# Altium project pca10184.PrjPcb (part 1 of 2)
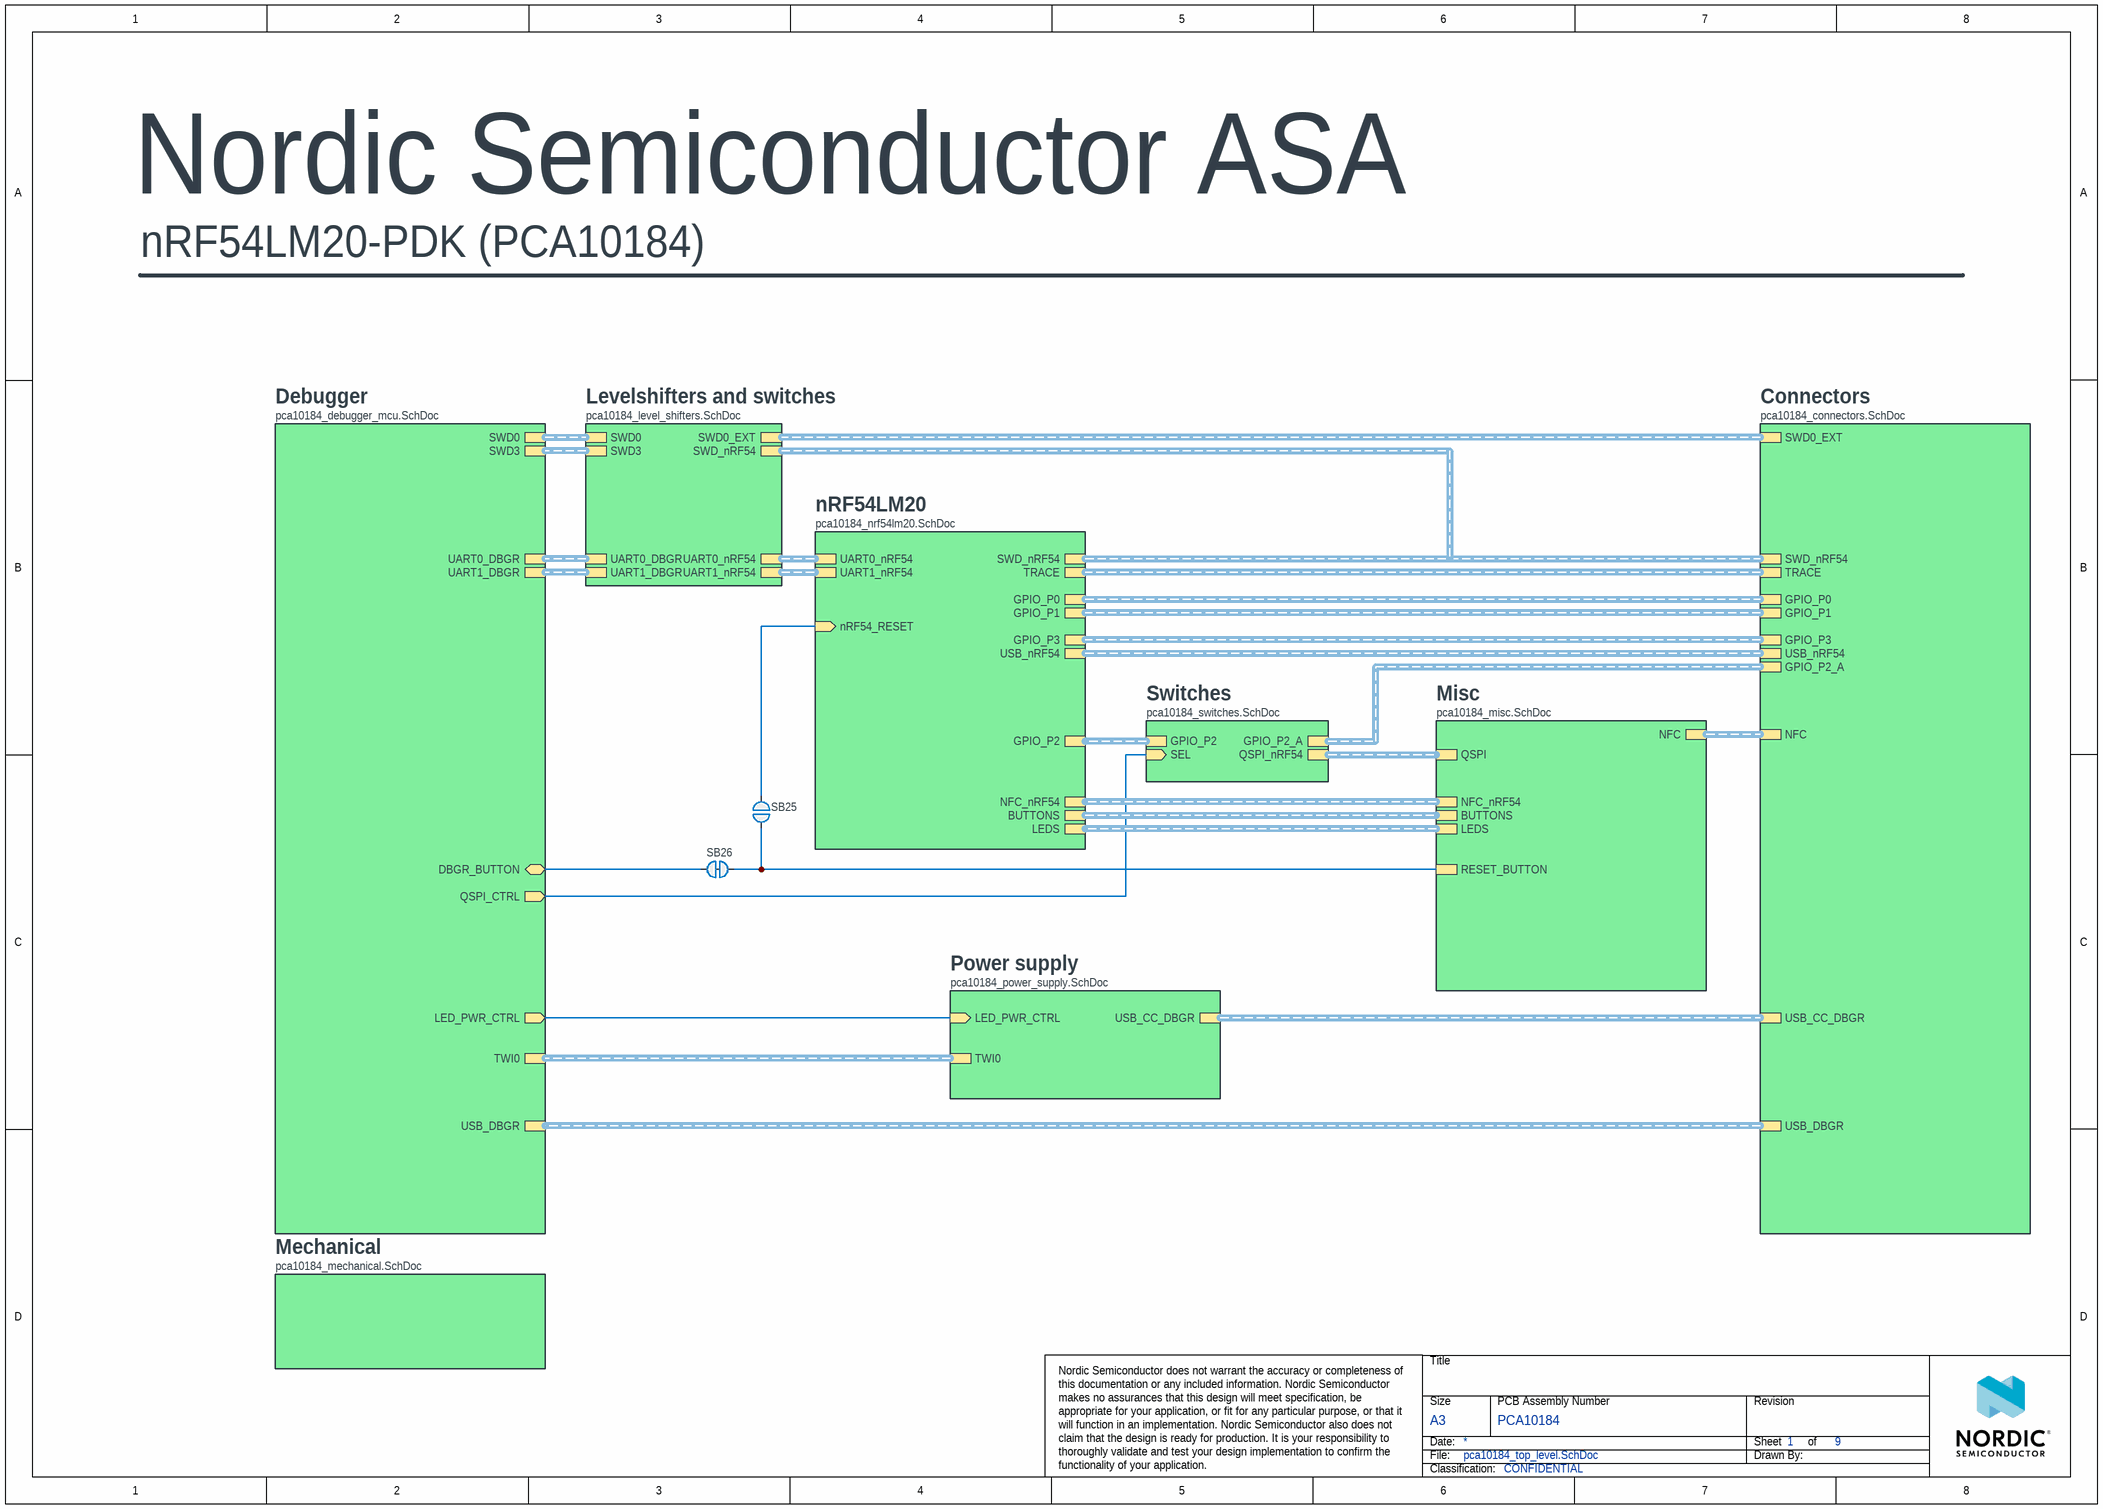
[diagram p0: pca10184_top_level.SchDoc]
SurfaceFinish: ENIG; SoldermaskColor: Blue; SilkscreenColor: White; ProductName: nRF54LM20 Preview Development Kit; PCBRevision: 0227GETR; PCBNumber: 400861; PCARevision: 0.3.4; PCAName: PCA10184; Organization: Nordic Semiconductor; NrOfLayers: 8; Dielectric: FR-4; Designer: GETR; Compliance: RoHS, REACH, Halogen-Free; Classification: CONFIDENTIAL; BoardTitle: nRF54LM20-PDK; BoardThickness: 1.6 mm
9 sheets, 284 parts. Net scope: hierarchical (ports join the sheet entries above them; power ports are global).
Board files: 400861.PcbDoc, 400861_panel.PcbDoc
Sheets:
  pca10184_top_level.SchDoc
    Debugger = pca10184_debugger_mcu.SchDoc
    Power supply = pca10184_power_supply.SchDoc
    nRF54LM20 = pca10184_nrf54lm20.SchDoc
    Connectors = pca10184_connectors.SchDoc
    Mechanical = pca10184_mechanical.SchDoc
    Misc = pca10184_misc.SchDoc
    Levelshifters and switches = pca10184_level_shifters.SchDoc
    Switches = pca10184_switches.SchDoc

## Sheet pca10184_top_level.SchDoc: =ProductName
size A3; Author: GETR; CompanyName: Nordic Semiconductor; DrawnBy: GETR; DocumentNumber: 1; Revision: 0.3.4; SheetNumber: 1; SheetTotal: 9

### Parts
SB25  Solderbridge  [Solderbridge]  (value not drawn)  (no BOM)
SB26  Solderbridge  [Solderbridge_Shorted]  (value not drawn)  (net tie, no BOM)

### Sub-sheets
Connectors = pca10184_connectors.SchDoc: SWD_nRF54 (harness SWD), NFC (harness NFC), GPIO_P0 (harness GPIO_P0), GPIO_P1 (harness GPIO_P1), GPIO_P3 (harness GPIO_P3), SWD0_EXT (harness SWD), USB_nRF54 (harness USB), USB_DBGR (harness USB), USB_CC_DBGR (harness USB_CC), TRACE (harness TRACE), GPIO_P2_A (harness GPIO_P2)
Debugger = pca10184_debugger_mcu.SchDoc: UART0_DBGR (harness UART_DBGR), UART1_DBGR (harness UART_DBGR), SWD0 (harness SWD), SWD3 (harness SWD), USB_DBGR (harness USB), TWI0 (harness TWI), DBGR_BUTTON (bidir), LED_PWR_CTRL (out), QSPI_CTRL (out)
Levelshifters and switches = pca10184_level_shifters.SchDoc: SWD0 (harness SWD), SWD0_EXT (harness SWD), UART0_nRF54 (harness UART), UART1_nRF54 (harness UART), SWD3 (harness SWD), SWD_nRF54 (harness SWD), UART0_DBGR (harness UART_DBGR), UART1_DBGR (harness UART_DBGR)
Mechanical = pca10184_mechanical.SchDoc: no entries
Misc = pca10184_misc.SchDoc: NFC_nRF54 (harness NFC), NFC (harness NFC), BUTTONS (harness BUTTONS), LEDS (harness LEDS), QSPI (harness QSPI), RESET_BUTTON
nRF54LM20 = pca10184_nrf54lm20.SchDoc: GPIO_P0 (harness GPIO_P0), GPIO_P1 (harness GPIO_P1), GPIO_P2 (harness GPIO_P2), GPIO_P3 (harness GPIO_P3), USB_nRF54 (harness USB), BUTTONS (harness BUTTONS), LEDS (harness LEDS), NFC_nRF54 (harness NFC), UART0_nRF54 (harness UART), UART1_nRF54 (harness UART), SWD_nRF54 (harness SWD), TRACE (harness TRACE), nRF54_RESET (in)
Power supply = pca10184_power_supply.SchDoc: TWI0 (harness TWI), LED_PWR_CTRL (in), USB_CC_DBGR (harness USB_CC)
Switches = pca10184_switches.SchDoc: GPIO_P2 (harness GPIO_P2), GPIO_P2_A (harness GPIO_P2), QSPI_nRF54 (harness QSPI), SEL (in)

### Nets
DBGR_BUTTON: SB26.2 ; sheet Debugger/DBGR_BUTTON
LED_PWR_CTRL: sheet Debugger/LED_PWR_CTRL, sheet Power supply/LED_PWR_CTRL
nRF54_RESET: SB25.1 ; sheet nRF54LM20/nRF54_RESET
QSPI_CTRL: sheet Debugger/QSPI_CTRL, sheet Switches/SEL
NetSB22_1: SB25.2 SB26.1 ; sheet Misc/RESET_BUTTON

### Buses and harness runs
harness sheet Connectors/GPIO_P0 = sheet nRF54LM20/GPIO_P0
harness sheet Connectors/GPIO_P1 = sheet nRF54LM20/GPIO_P1
harness sheet Connectors/GPIO_P2_A = sheet Switches/GPIO_P2_A
harness sheet Connectors/GPIO_P3 = sheet nRF54LM20/GPIO_P3
harness sheet Connectors/NFC = sheet Misc/NFC
harness sheet Connectors/SWD0_EXT = sheet Levelshifters and switches/SWD0_EXT
harness sheet Connectors/SWD_nRF54 = sheet Levelshifters and switches/SWD_nRF54 = sheet nRF54LM20/SWD_nRF54
harness sheet Connectors/TRACE = sheet nRF54LM20/TRACE
harness sheet Connectors/USB_CC_DBGR = sheet Power supply/USB_CC_DBGR
harness sheet Connectors/USB_DBGR = sheet Debugger/USB_DBGR
harness sheet Connectors/USB_nRF54 = sheet nRF54LM20/USB_nRF54
harness sheet Debugger/SWD0 = sheet Levelshifters and switches/SWD0
harness sheet Debugger/SWD3 = sheet Levelshifters and switches/SWD3
harness sheet Debugger/TWI0 = sheet Power supply/TWI0
harness sheet Debugger/UART0_DBGR = sheet Levelshifters and switches/UART0_DBGR
harness sheet Debugger/UART1_DBGR = sheet Levelshifters and switches/UART1_DBGR
harness sheet Levelshifters and switches/UART0_nRF54 = sheet nRF54LM20/UART0_nRF54
harness sheet Levelshifters and switches/UART1_nRF54 = sheet nRF54LM20/UART1_nRF54
harness sheet Misc/BUTTONS = sheet nRF54LM20/BUTTONS
harness sheet Misc/LEDS = sheet nRF54LM20/LEDS
harness sheet Misc/NFC_nRF54 = sheet nRF54LM20/NFC_nRF54
harness sheet Misc/QSPI = sheet Switches/QSPI_nRF54
harness sheet nRF54LM20/GPIO_P2 = sheet Switches/GPIO_P2

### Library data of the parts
SB25 = Solderbridge: Manufacturer: N.A.; Part number NEMS: 100500458; Pad Count: 2; Component Status: Active; System: Connector
SB26 = Solderbridge Shorted: Shorted Solderbridge; Manufacturer: N.A.; Part number NEMS: 100500459; Pad Count: 2; Component Status: Active; System: Connector

## Sheet pca10184_debugger_mcu.SchDoc: =ProductName + ' - Debugger'
size A3; Author: GETR; CompanyName: Nordic Semiconductor; DrawnBy: GETR; DocumentNumber: 3; Revision: 0.3.4; SheetNumber: 3; SheetTotal: 9
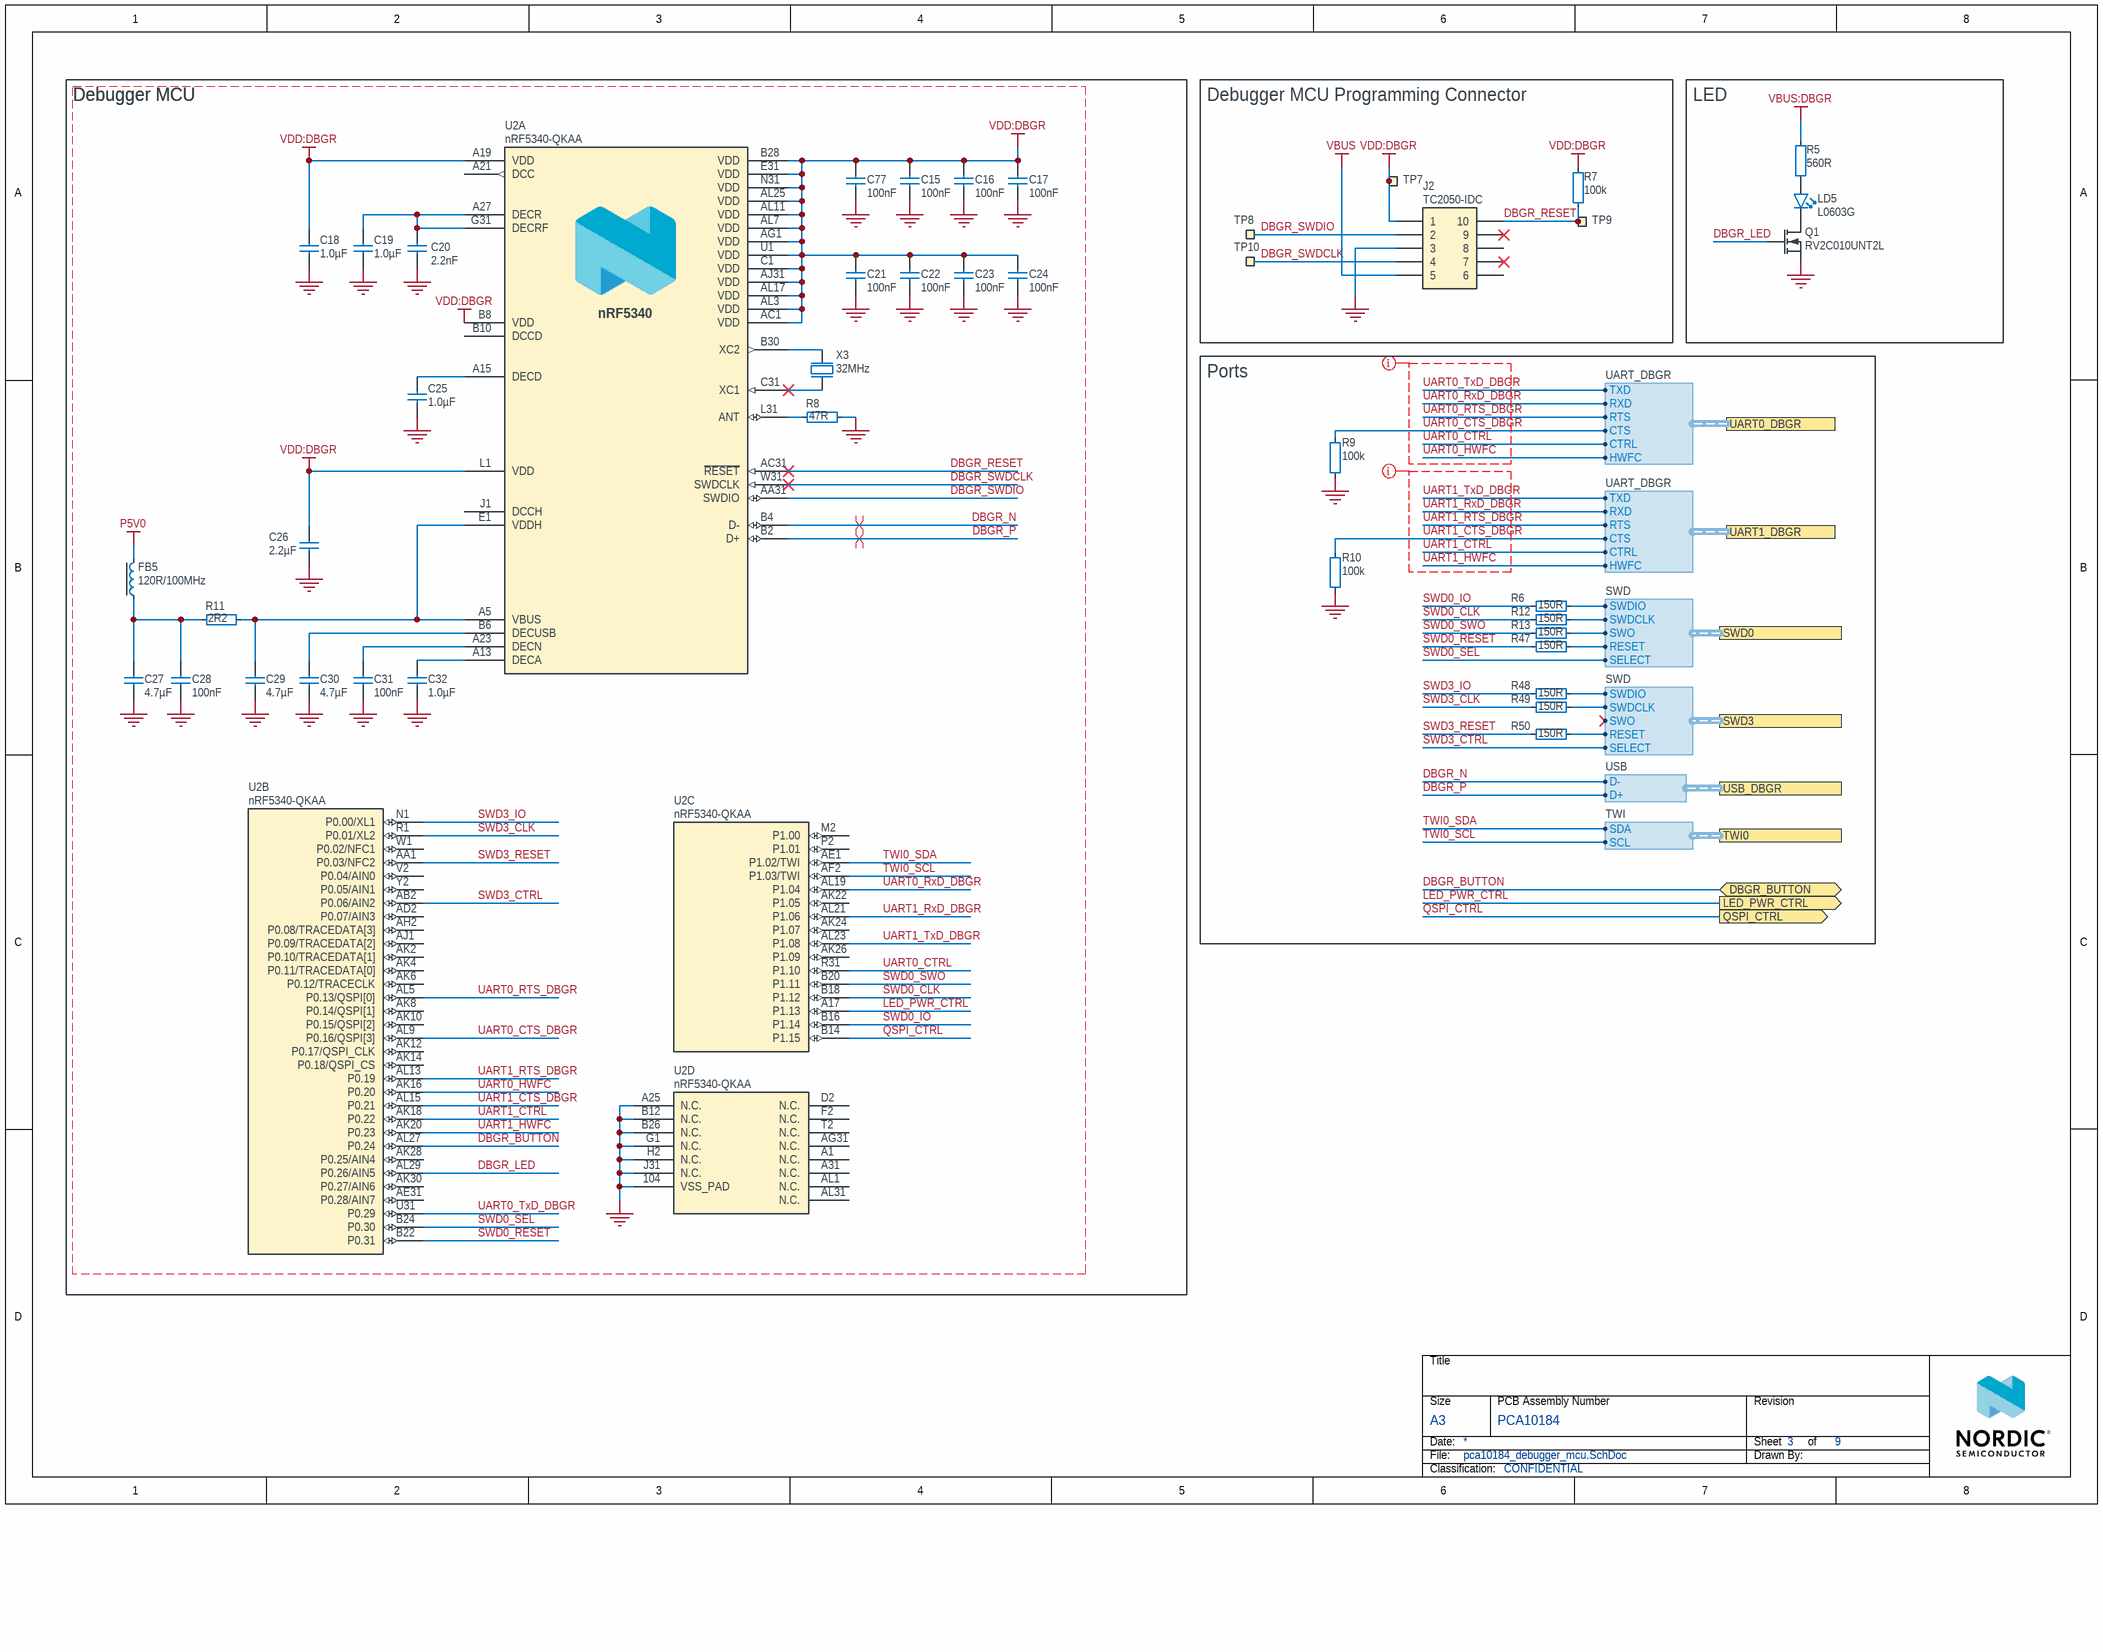
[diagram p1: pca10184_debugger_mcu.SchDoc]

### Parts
C15  100nF  [CAPC0603X03L_C]
C16  100nF  [CAPC0603X03L_C]
C17  100nF  [CAPC0603X03L_C]
C18  1.0µF  [CAPC1005X04L]
C19  1.0µF  [CAPC1005X04L]
C20  2.2nF  [CAPC0603X03L_C]
C21  100nF  [CAPC0603X03L_C]
C22  100nF  [CAPC0603X03L_C]
C23  100nF  [CAPC0603X03L_C]
C24  100nF  [CAPC0603X03L_C]
C25  1.0µF  [CAPC1005X04L]
C26  2.2µF  [CAPC1608X06L]
C27  4.7µF  [CAPC1608X06L]
C28  100nF  [CAPC0603X03L_C]
C29  4.7µF  [CAPC1608X06L]
C30  4.7µF  [CAPC1608X06L]
C31  100nF  [CAPC0603X03L_C]
C32  1.0µF  [CAPC1005X04L]
C77  100nF  [CAPC0603X03L_C]
FB5  120R/100MHz  [INDC1005X04L_C2]
J2  TC2050-IDC  [TC2050-IDC-NLFP]  (no BOM)
LD5  L0603G  [LED_0603_G]
Q1  RV2C010UNT2L  [DFN65P100X40-3L]
R5  560R  [RESC0603X03L_C]
R6  150R  [RESC0603X03L_C]
R7  100k  [RESC0603X03L_C]
R8  47R  [RESC0603X03L_C]
R9  100k  [RESC0603X03L_C]
R10  100k  [RESC0603X03L_C]
R11  2R2  [RESC1608X06L]
R12  150R  [RESC0603X03L_C]
R13  150R  [RESC0603X03L_C]
R47  150R  [RESC0603X03L_C]
R48  150R  [RESC0603X03L_C]
R49  150R  [RESC0603X03L_C]
R50  150R  [RESC0603X03L_C]
TP7  Ø1.5mm,SMD  [TP_SMD_D1.5mm]  (value not drawn)  (no BOM)
TP8  Ø1.5mm,SMD  [TP_SMD_D1.5mm]  (value not drawn)  (no BOM)
TP9  Ø1.5mm,SMD  [TP_SMD_D1.5mm]  (value not drawn)  (no BOM)
TP10  Ø1.5mm,SMD  [TP_SMD_D1.5mm]  (value not drawn)  (no BOM)
U2  nRF5340-QKAA  [AQFN40P700X700X85_HS-99N]  (parts A,B,C,D of 4)
X3  32MHz  [BT-XTAL_2016]

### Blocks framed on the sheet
Debugger MCU Programming Connector: J2 R7 TP7-TP10
LED: LD5 Q1 R5
Ports: R6 R9 R10 R12 R13 R47-R50

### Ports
DBGR_BUTTON (bidir), LED_PWR_CTRL (out), QSPI_CTRL (out), SWD0 (harness SWD), SWD3 (harness SWD), TWI0 (harness TWI), UART0_DBGR (harness UART_DBGR), UART1_DBGR (harness UART_DBGR), USB_DBGR (harness USB)

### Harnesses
UART_DBGR: RTS, CTS, RXD, TXD, HWFC, CTRL
SWD: SWDIO, SWDCLK, SWO, RESET, SELECT
USB: D+, D-
TWI: SCL, SDA

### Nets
GND: C15.2 C16.2 C17.2 C18.2 C19.1 C20.2 C21.2 C22.2 C23.2 C24.2 C25.1 C26.2 C27.2 C28.2 C29.2 C30.2 C31.2 C32.1 C77.2 J2.3 Q1.2(S) R8.2 R9.2 R10.2 U2.104(VSS_PAD) U2.A25(N.C.) U2.B12(N.C.) U2.B26(N.C.) U2.G1(N.C.) U2.H2(N.C.) U2.J31(N.C.) X3.2(GND) X3.4(GND)
P5V0: FB5.2
VBUS: J2.5
VBUS:DBGR: R5.2
VDD:DBGR: C15.1 C16.1 C17.1 C18.1 C21.1 C22.1 C23.1 C24.1 C26.1 C77.1 J2.1 R7.2 TP7.1 U2.A19(VDD) U2.AC1(VDD) U2.AG1(VDD) U2.AJ31(VDD) U2.AL3(VDD) U2.AL7(VDD) U2.AL11(VDD) U2.AL17(VDD) U2.AL25(VDD) U2.B8(VDD) U2.B28(VDD) U2.C1(VDD) U2.E31(VDD) U2.L1(VDD) U2.N31(VDD) U2.U1(VDD)
DBGR_BUTTON: U2.AL27(P0.24) ; port DBGR_BUTTON
DBGR_LED: Q1.1(G) U2.AL29(P0.26/AIN5)
DBGR_N: U2.B4(D-) ; port USB_DBGR.D-
DBGR_P: U2.B2(D+) ; port USB_DBGR.D+
DBGR_RESET: J2.10 R7.1 TP9.1 U2.AC31(~{RESET})
DBGR_SWDCLK: J2.4 TP10.1 U2.W31(SWDCLK)
DBGR_SWDIO: J2.2 TP8.1 U2.AA31(SWDIO)
LED_PWR_CTRL: U2.A17(P1.13) ; port LED_PWR_CTRL
QSPI_CTRL: U2.B14(P1.15) ; port QSPI_CTRL
SWD0_CLK: R12.1 U2.B18(P1.12)
SWD0_IO: R6.1 U2.B16(P1.14)
SWD0_RESET: R47.1 U2.B22(P0.31)
SWD0_SEL: U2.B24(P0.30) ; port SWD0.SELECT
SWD0_SWO: R13.1 U2.B20(P1.11)
SWD3_CLK: R49.1 U2.R1(P0.01/XL2)
SWD3_CTRL: U2.AB2(P0.06/AIN2) ; port SWD3.SELECT
SWD3_IO: R48.1 U2.N1(P0.00/XL1)
SWD3_RESET: R50.1 U2.AA1(P0.03/NFC2)
TWI0_SCL: U2.AF2(P1.03/TWI) ; port TWI0.SCL
TWI0_SDA: U2.AE1(P1.02/TWI) ; port TWI0.SDA
UART0_CTRL: U2.R31(P1.10) ; port UART0_DBGR.CTRL
UART0_CTS_DBGR: R9.1 U2.AL9(P0.16/QSPI[3]) ; port UART0_DBGR.CTS
UART0_HWFC: U2.AK16(P0.20) ; port UART0_DBGR.HWFC
UART0_RTS_DBGR: U2.AL5(P0.13/QSPI[0]) ; port UART0_DBGR.RTS
UART0_RxD_DBGR: U2.AL19(P1.04) ; port UART0_DBGR.RXD
UART0_TxD_DBGR: U2.U31(P0.29) ; port UART0_DBGR.TXD
UART1_CTRL: U2.AK18(P0.22) ; port UART1_DBGR.CTRL
UART1_CTS_DBGR: R10.1 U2.AL15(P0.21) ; port UART1_DBGR.CTS
UART1_HWFC: U2.AK20(P0.23) ; port UART1_DBGR.HWFC
UART1_RTS_DBGR: U2.AL13(P0.19) ; port UART1_DBGR.RTS
UART1_RxD_DBGR: U2.AL21(P1.06) ; port UART1_DBGR.RXD
UART1_TxD_DBGR: U2.AL23(P1.08) ; port UART1_DBGR.TXD
NetC19_2: C19.2 C20.1 U2.A27(DECR) U2.G31(DECRF)
NetC25_2: C25.2 U2.A15(DECD)
NetC27_1: C27.1 C28.1 FB5.1 R11.1
NetC29_1: C29.1 R11.2 U2.A5(VBUS) U2.E1(VDDH)
NetC30_1: C30.1 U2.B6(DECUSB)
NetC31_1: C31.1 U2.A23(DECN)
NetC32_2: C32.2 U2.A13(DECA)
NetLD5_1: LD5.1(C) Q1.3(D)
NetLD5_2: LD5.2(A) R5.1
NetR6_2: R6.2 ; port SWD0.SWDIO
NetR8_1: R8.1 U2.L31(ANT)
NetR12_2: R12.2 ; port SWD0.SWDCLK
NetR13_2: R13.2 ; port SWD0.SWO
NetR47_2: R47.2 ; port SWD0.RESET
NetR48_2: R48.2 ; port SWD3.SWDIO
NetR49_2: R49.2 ; port SWD3.SWDCLK
NetR50_2: R50.2 ; port SWD3.RESET
NetU2_B30: U2.B30(XC2) X3.3(out)
NetU2_C31: U2.C31(XC1) X3.1(inp)

Not connected (* = marked no-connect by the designer): J2 6 7* 8 9*; U2 A1(N.C.) A21(DCC) A31(N.C.) AD2(P0.07/AIN3) AE31(P0.28/AIN7) AG31(N.C.) AH2(P0.08/TRACEDATA[3]) AJ1(P0.09/TRACEDATA[2]) AK2(P0.10/TRACEDATA[1]) AK4(P0.11/TRACEDATA[0]) AK6(P0.12/TRACECLK) AK8(P0.14/QSPI[1]) AK10(P0.15/QSPI[2]) AK12(P0.17/QSPI_CLK) AK14(P0.18/QSPI_CS) AK22(P1.05) AK24(P1.07) AK26(P1.09) AK28(P0.25/AIN4) AK30(P0.27/AIN6) AL1(N.C.) AL31(N.C.) B10(DCCD) D2(N.C.) F2(N.C.) J1(DCCH) M2(P1.00) P2(P1.01) T2(N.C.) V2(P0.04/AIN0) W1(P0.02/NFC1) Y2(P0.05/AIN1)

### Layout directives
net class UART0: UART0_CTRL, UART0_CTS_DBGR, UART0_HWFC, UART0_RTS_DBGR, UART0_RxD_DBGR, UART0_TxD_DBGR
net class UART1: UART1_CTRL, UART1_CTS_DBGR, UART1_HWFC, UART1_RTS_DBGR, UART1_RxD_DBGR, UART1_TxD_DBGR
differential pair; differential pair class IMCU; net class USB: DBGR_N, DBGR_P

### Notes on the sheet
- Debugger MCU

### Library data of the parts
C15-C17 C21-C24 C28 C31 C77 = C0201-100n: Capacitor, X5R, ±10%, 100nF, 16V; Manufacturer: N.A.; Part number IPS: 00000001248, 00000002505; Part number Norautron: 262071862; Part number NEMS: 100200078; Pad Count: 2; Component Status: Active
C18 C19 C25 C32 = C0402-1µ0-6.3V-X5R-10%: Capacitor, X5R, ±10%, 6.3V; Manufacturer: N.A.; Part number Norautron: 26207137; Part number NEMS: 100200498; Pad Count: 2; Component Status: Active
C20 = C0201-2n2: Capacitor, X7R, ±10%, 10V; Manufacturer: N.A.; Part number IPS: 00000001778; Part number Norautron: 26470002; Part number NEMS: 100200060; Pad Count: 2; Component Status: Active
C26 = C0603-2µ2-6.3V-X7R: Capacitor, X7R, ±10%, 2.2µF, 6.3V; Manufacturer: N.A.; Part number NEMS: 100200272; Artikkelnr Noca: 20039322; Pad Count: 2; Component Status: Active
C27 C29 = C0603-4µ7-10V-X7S: Capacitor, X7S, ±10%, 10V; Manufacturer: N.A.; Part number IPS: 00000001779; Part number NEMS: 100200351; Pad Count: 2; Artikkelnr Noca: 20030013; Component Status: Active
C30 = C0603-4µ7-6.3V-X7R: Capacitor, X7R, ±10%, 6.3V; Manufacturer: Samsung Electro-Mechanics America; Manufacturer Part Number: CL10B475KQ8NQNC; Part number IPS: 00000002541; Part number Norautron: N.A.; Part number NEMS: 100200350; Pad Count: 2; Artikkelnr Noca: 20039473; Component Status: Active
FB5 = FB0402-120R@100MHz-1200mA-BLM15EX121SN1_C2: Ferrite Bead, 120 Ohm @ 100MHz, 1200mA, 75 mOhm Max; Manufacturer: Murata; Part number NEMS: 100300431, 100300416; Component Status: Active; Pad Count: 2; Note: N.A.
J2 = TC2050-IDC-NLFP: CBL PLUG-OF-NAILS 10-PIN; Manufacturer: Tag-Connect LLC; Part number NEMS: 100500463; Artikkelnr Noca: N.A.; Pad Count: 10; Component Status: Active; System: Connector
LD5 = VS 25C7M5: LED, Green, 0603, 573nm, Vf=2.0V, 24mcd, - 40 to +85°C; Manufacturer: Victory Electronics; Part number IPS: 00000001274, 00000009961; Part number Norautron: 26313411; Part number NEMS: 101400097; Pad Count: 2; Note: N.A.; Artikkelnr Noca: 13019193; Component Status: Active
Q1 = RV2C010UNT2L: N-Channel MOSFET, 20V, 1A, 470mOhm, 400mW, -55°C ~ 150°C; Manufacturer: Rohm Semiconductor; Part number IPS: 00000009976; Part number Norautron: 26320026; Part number NEMS: 101300132; Note: N.A.; Artikkelnr Noca: 35010020; Pad Count: 3; Component Status: Active
R5 = R0201-560: Resistor, ±1%, 0.05W; Manufacturer: N.A.; Part number NEMS: 100100038; Note: Chip Res 1%; Pad Count: 2; Component Status: Active
R6 R12 R13 R47-R50 = R0201-150: Resistor, ±1%, 0.05W; Manufacturer: N.A.; Part number IPS: 00000001420; Part number NEMS: 100100029; Note: Chip Res 1%; Pad Count: 2; Component Status: Active
R7 R9 R10 = R0201-100k: Resistor, ±1%, 0.05W; Manufacturer: N.A.; Part number IPS: 00000001419; Part number Norautron: 26108487; Part number NEMS: 100100080; Note: Chip Res 1%; Pad Count: 2; Component Status: Active
R8 = R0201-47R: Resistor, ±1%, 0.05W; Manufacturer: N.A.; Part number IPS: 00000004794; Part number Norautron: 26108300; Part number NEMS: 100100022; Component Status: Active; Pad Count: 2; Note: Chip Res 1%
R11 = R0603-2R2: RES 2.2 OHM 1% 1/10W 0603; Manufacturer: N.A.; Part number NEMS: 100100736; Pad Count: 2; Note: Chip Res 1%; Component Status: Active
TP7-TP10 = TP_SMD_Ø1.5MM: 1.5mm circular SMD testpad; Manufacturer: Nordic Semiconductor; Manufacturer Part Number: N.A.; Part number NEMS: 100500477; Pad Count: 1; Component Status: Active
U2 = nRF5340-QKAAD0: Multi-protocol Bluetooth Low Energy, IEEE 802.15.4, ANT and 2.4GHz proprietary system-on-chip; Manufacturer: Nordic Semiconductor; Part number Norautron: NOD26470035; Part number NEMS: 102000216; Pad Count: 98; Note: N.A.; Component Status: Active
X3 = XTAL_SMD2016_32MHz_8pF_Golledge: XTAL SMD 2016, 32MHz, Cl=8pF, Tol: ±10ppm, Stab: ±15ppm; Manufacturer Part Number: MP06003; Part number IPS: 00000001431; Part number Norautron: N.A.; Part number NEMS: 101600041; Note: XTAL SMD 32.000MHz; Artikkelnr Noca: 22010050; Pad Count: 4; Component Status: Active

## Sheet pca10184_power_supply.SchDoc: =ProductName + ' - Power Supply'
size A3; Author: GETR; CompanyName: Nordic Semiconductor; DrawnBy: GETR; DocumentNumber: 6; Revision: 0.3.4; SheetNumber: 6; SheetTotal: 9
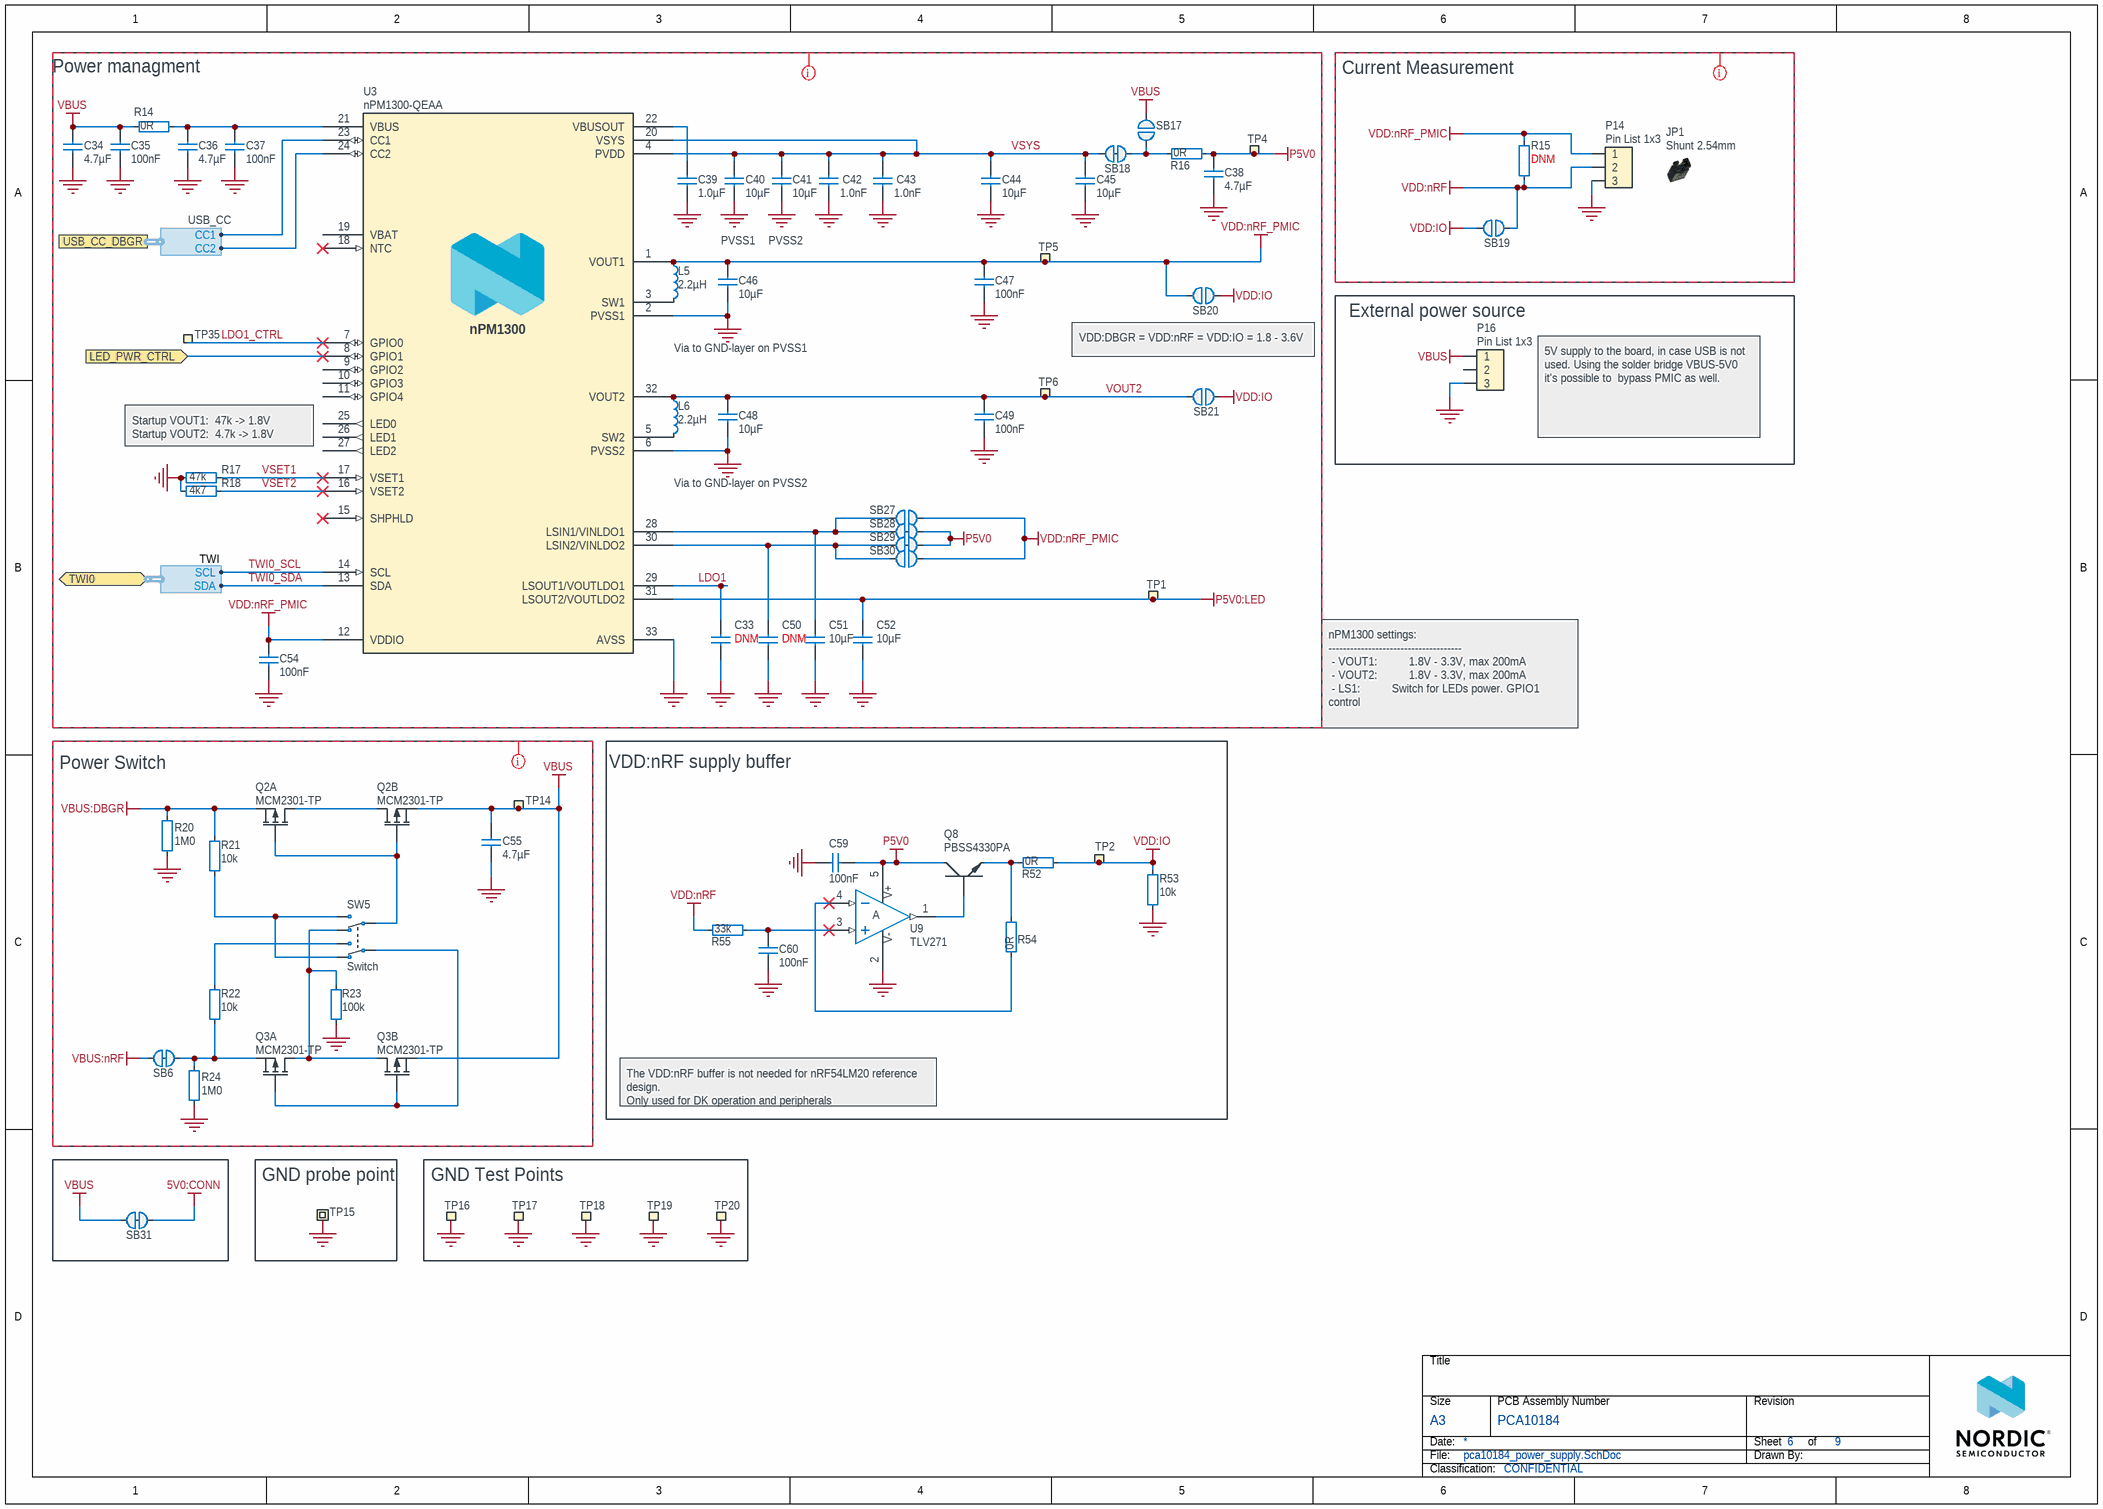
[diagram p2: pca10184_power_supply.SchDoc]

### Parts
C33  DNM  [CAPC1608X06L]
C34  4.7µF  [CAPC1005X04L_C2]
C35  100nF  [CAPC0603X03L_C]
C36  4.7µF  [CAPC1005X04L_C2]
C37  100nF  [CAPC0603X03L_C]
C38  4.7µF  [CAPC1005X04L_C2]
C39  1.0µF  [CAPC1005X04L]
C40  10µF  [CAPC1608X06L]
C41  10µF  [CAPC1608X06L]
C42  1.0nF  [CAPC0603X03L_C]
C43  1.0nF  [CAPC0603X03L_C]
C44  10µF  [CAPC1608X06L]
C45  10µF  [CAPC1608X06L]
C46  10µF  [CAPC1608X06L]
C47  100nF  [CAPC0603X03L_C]
C48  10µF  [CAPC1608X06L]
C49  100nF  [CAPC0603X03L_C]
C50  DNM  [CAPC1608X06L]
C51  10µF  [CAPC1608X06L]
C52  10µF  [CAPC1608X06L]
C54  100nF  [CAPC0603X03L_C]
C55  4.7µF  [CAPC1608X06L]
C59  100nF  [CAPC0603X03L_C]
C60  100nF  [CAPC0603X03L_C]
JP1  Shunt 2.54mm  [Shunt_2.54mm_Vertical]
L5  2.2µH  [INDC2016X10N]
L6  2.2µH  [INDC2016X10N]
P14  Pin List 1x3  [LIST_1x3_SMD]
P16  Pin List 1x3  [LIST_1x3_SMD]
Q2  MCM2301-TP  [DFN65P200X200X80_HS-6N]  (parts A,B of 2)
Q3  MCM2301-TP  [DFN65P200X200X80_HS-6N]  (parts A,B of 2)
Q8  PBSS4330PA  [DFN105P200X65-3N_v2]
R14  0R  [RESC1005X04L]
R15  DNM  [RESC1005X04L]
R16  0R  [RESC1005X04L]
R17  47k  [RESC0603X03L_C]
R18  4k7  [RESC0603X03L_C]
R20  1M0  [RESC0603X03L_C]
R21  10k  [RESC0603X03L_C]
R22  10k  [RESC0603X03L_C]
R23  100k  [RESC0603X03L_C]
R24  1M0  [RESC0603X03L_C]
R52  0R  [RESC0603X03L_C]
R53  10k  [RESC0603X03L_C]
R54  0R  [RESC0603X03L_C]
R55  33k  [RESC0603X03L_C]
SB6  Solderbridge  [Solderbridge_Shorted_Power]  (value not drawn)  (net tie, no BOM)
SB17  Solderbridge  [Solderbridge]  (value not drawn)  (no BOM)
SB18  Solderbridge  [Solderbridge_Shorted_Power]  (value not drawn)  (net tie, no BOM)
SB19  Solderbridge  [Solderbridge]  (value not drawn)  (no BOM)
SB20  Solderbridge  [Solderbridge]  (value not drawn)  (no BOM)
SB21  Solderbridge  [Solderbridge]  (value not drawn)  (no BOM)
SB27  Solderbridge  [Solderbridge]  (value not drawn)  (no BOM)
SB28  Solderbridge  [Solderbridge_Shorted]  (value not drawn)  (net tie, no BOM)
SB29  Solderbridge  [Solderbridge_Shorted]  (value not drawn)  (net tie, no BOM)
SB30  Solderbridge  [Solderbridge]  (value not drawn)  (no BOM)
SB31  Solderbridge  [Solderbridge_Shorted_Power]  (value not drawn)  (net tie, no BOM)
SW5  Switch  [JS102011JAQN]
TP1  Ø1.5mm,SMD  [TP_SMD_D1.5mm]  (value not drawn)  (no BOM)
TP2  Ø1.5mm,SMD  [TP_SMD_D1.5mm]  (value not drawn)  (no BOM)
TP4  Ø1.5mm,SMD  [TP_SMD_D1.5mm]  (value not drawn)  (no BOM)
TP5  Ø1.5mm,SMD  [TP_SMD_D1.5mm]  (value not drawn)  (no BOM)
TP6  Ø1.5mm,SMD  [TP_SMD_D1.5mm]  (value not drawn)  (no BOM)
TP14  Ø1.5mm,SMD  [TP_SMD_D1.5mm]  (value not drawn)  (no BOM)
TP15  TP  [S1751]  (value not drawn)
TP16  Ø1.5mm,SMD  [TP_SMD_D1.5mm]  (value not drawn)  (no BOM)
TP17  Ø1.5mm,SMD  [TP_SMD_D1.5mm]  (value not drawn)  (no BOM)
TP18  Ø1.5mm,SMD  [TP_SMD_D1.5mm]  (value not drawn)  (no BOM)
TP19  Ø1.5mm,SMD  [TP_SMD_D1.5mm]  (value not drawn)  (no BOM)
TP20  Ø1.5mm,SMD  [TP_SMD_D1.5mm]  (value not drawn)  (no BOM)
TP35  Ø0.7mm,SMD  [TP_SMD_D0.7mm]  (value not drawn)  (no BOM)
U3  nPM1300-QEAA  [Nordic_QFN50P500X500X90-33N]
U9  TLV271  [SOT95P280X145-5N]

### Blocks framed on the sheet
Power managment: C33-C52 C54 L5 L6 R14 R16-R18 SB17 SB18 SB20 SB21 SB27-SB30 TP1 TP4-TP6 TP35 U3
Current Measurement: JP1 P14 R15 SB19
External power source: P16
Power Switch: C55 Q2 Q3 R20-R24 SB6 SW5 TP14
VDD:nRF supply buffer: C59 C60 Q8 R52-R55 TP2 U9
GND probe point: TP15
GND Test Points: TP16-TP20

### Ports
LED_PWR_CTRL (in), TWI0 (bidir, harness TWI), USB_CC_DBGR (harness USB_CC)

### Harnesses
USB_CC: CC2, CC1
TWI: SCL, SDA

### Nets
5V0:CONN: SB31.1
GND: C33.1 C34.1 C35.1 C36.1 C37.1 C38.1 C39.1 C40.1 C41.1 C42.1 C43.1 C44.1 C45.1 C46.1 C47.1 C48.1 C49.1 C50.1 C51.1 C52.1 C54.2 C55.1 C59.2 C60.2 P14.3 P16.3 R17.2 R18.2 R20.2 R23.2 R24.2 R53.1 TP15.1 TP16.1 TP17.1 TP18.1 TP19.1 TP20.1 U3.2(PVSS1) U3.6(PVSS2) U3.33(AVSS) U9.2(VSS)
P5V0: C38.2 C59.1 Q8.3(C) R16.2 SB28.1 SB29.1 TP4.1 U9.5(VDD)
P5V0:LED: C52.2 TP1.1 U3.31(LSOUT2/VOUTLDO2)
VBUS: C34.2 C35.2 C55.2 P16.1 Q2.4(S2) Q3.4(S2) R14.1 SB17.1 SB31.2 TP14.1
VBUS:DBGR: Q2.1(S1) R20.1 R21.1
VBUS:nRF: SB6.2
VDD:IO: R52.2 R53.2 SB19.1 SB20.1 SB21.1 TP2.1
VDD:nRF: P14.2 R15.1 R55.1 SB19.2
VDD:nRF_PMIC: C46.2 C47.2 C54.1 L5.1 P14.1 R15.2 SB20.2 SB27.1 SB30.1 TP5.1 U3.1(VOUT1) U3.12(VDDIO)
LDO1: C33.2 U3.29(LSOUT1/VOUTLDO1)
LDO1_CTRL: TP35.1 U3.7(GPIO0)
LED_PWR_CTRL: U3.8(GPIO1) ; port LED_PWR_CTRL
TWI0_SCL: U3.14(SCL) ; port TWI0.SCL
TWI0_SDA: U3.13(SDA) ; port TWI0.SDA
VOUT2: C48.2 C49.2 L6.1 SB21.2 TP6.1 U3.32(VOUT2)
VSET1: R17.1 U3.17(VSET1)
VSET2: R18.1 U3.16(VSET2)
VSYS: C40.2 C41.2 C42.2 C43.2 C44.2 C45.2 SB18.2 U3.4(PVDD) U3.20(VSYS)
NetC36_2: C36.2 C37.2 R14.2 U3.21(VBUS)
NetC39_2: C39.2 U3.22(VBUSOUT)
NetC50_2: C50.2 SB29.2 SB30.2 U3.30(LSIN2/VINLDO2)
NetC51_2: C51.2 SB27.2 SB28.2 U3.28(LSIN1/VINLDO1)
NetC60_1: C60.1 R55.2 U9.3(IN+)
NetJ4_A5: U3.23(CC1) ; port USB_CC_DBGR.CC1
NetJ4_B5: U3.24(CC2) ; port USB_CC_DBGR.CC2
NetL5_2: L5.2 U3.3(SW1)
NetL6_2: L6.2 U3.5(SW2)
NetQ2_2: Q2.2(G1) Q2.5(G2) SW5.5(COM-2)
NetQ2_3: Q2.3(D2) Q2.6(D1)
NetQ3_1: Q3.1(S1) R22.2 R24.1 SB6.1
NetQ3_2: Q3.2(G1) Q3.5(G2) SW5.2(COM-1)
NetQ3_3: Q3.3(D2) Q3.6(D1) R23.1 SW5.6(N.C-2)
NetQ8_1: Q8.1(B) U9.1(OUT)
NetQ8_2: Q8.2(E) R52.1 R54.2
NetR16_1: R16.1 SB17.2 SB18.1
NetR21_2: R21.2 SW5.3(N.C-1) SW5.4(N.O-2)
NetR22_1: R22.1 SW5.1(N.O-1)
NetR54_1: R54.1 U9.4(IN-)

Not connected (* = marked no-connect by the designer): P16 2; U3 9(GPIO2) 10(GPIO3) 11(GPIO4) 15(SHPHLD)* 18(NTC)* 19(VBAT) 25(LED0) 26(LED1) 27(LED2)

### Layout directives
CompClassName: nPM1300: GND, LDO1, LDO1_CTRL, P5V0, P5V0:LED, TWI0_SCL, TWI0_SDA, VBUS, VDD:IO, VDD:nRF_PMIC, VOUT2, VSET1, VSET2, VSYS
CompClassName: Current measurments: GND, VDD:IO, VDD:nRF, VDD:nRF_PMIC
CompClassName: Power Switch: GND, VBUS, VBUS:DBGR, VBUS:nRF

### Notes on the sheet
- PVSS1
- PVSS2
- Via to GND-layer on PVSS1
- VDD:DBGR = VDD:nRF = VDD:IO = 1.8 - 3.6V
- Startup VOUT1:  47k -> 1.8V
  Startup VOUT2:  4.7k -> 1.8V
- 5V supply to the board, in case USB is not used. Using the solder bridge VBUS-5V0 it's possible to  bypass PMIC as well.
- Via to GND-layer on PVSS2
- nPM1300 settings:
  -------------------------------------
  - VOUT1:          1.8V - 3.3V, max 200mA
  - VOUT2:          1.8V - 3.3V, max 200mA
  - LS1:	         Switch for LEDs power. GPIO1 control
  VSYS current limit: 900mA
- The VDD:nRF buffer is not needed for nRF54LM20 reference design.
  Only used for DK operation and peripherals

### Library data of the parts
C33 C50 = C0603-10µ-10V-X5R: Capacitor, Ceramic, X5R, ±20%, 10V; Manufacturer: N.A.; Part number Norautron: 262085341; Part number NEMS: 100200481; Component Status: Active; Pad Count: 2; Value: 10µF; Assembly: Not mounted
C34 C36 C38 = C0402-4µ7-10V-X5R-GRM155R61A475MEAAD: Capacitor, X5R, ±20%, 10V; Manufacturer: Murata; Part number NEMS: 100200549, 100200415; Component Status: Active; Pad Count: 2; Artikkelnr Noca: N.A.
C35 C37 C47 C49 C54 = C0201-100n: as C15 on sheet pca10184_debugger_mcu
C39 = C0402-1µ0-10V-X5R: Capacitor, Ceramic, X5R, ±10%, 10V; Manufacturer: N.A.; Part number NEMS: 100200482; Component Status: Active; Pad Count: 2
C40 C41 C44-C46 C48 = C0603-10µ-10V-X7T-GRM188D71A106MA73: Capacitor, X7T, ±20%, 10V; Manufacturer: Murata; Manufacturer Part Number: GRM188D71A106MA73D; Part number IPS: 00000004696; Part number NEMS: 100200414; Component Status: Active; Pad Count: 2; Note: 10VDC; Artikkelnr Noca: N.A.
C42 C43 = C0201-1n0: Capacitor, X7R, ±10%, 25V; Manufacturer: N.A.; Part number IPS: 00000003206; Part number NEMS: 100200056; Component Status: Active; Pad Count: 2; Note: 16V
C51 C52 = C0603-10µ-10V-X5R: Capacitor, Ceramic, X5R, ±20%, 10V; Manufacturer: N.A.; Part number Norautron: 262085341; Part number NEMS: 100200481; Component Status: Active; Pad Count: 2
C55 = C0603-4µ7-25V-X5R: Capacitor, X5R, ±10%, 25V; Manufacturer: Murata; Manufacturer Part Number: GRM188R61E475KE11D; Part number NEMS: 100200352; Component Status: Active; Pad Count: 2; Artikkelnr Noca: N.A.
C59 C60 = C0201-100n: Capacitor, X5R, ±10%; Manufacturer: N.A.; Part number IPS: 00000001248, 00000002505; Part number Norautron: 262071862; Part number NEMS: 100200078; Pad Count: 2; Note: 16V; Component Status: Active
JP1 = SHUNT JUMPER 2.54mm Black Vertical: Shunt Jumper 2.54mm Black, open top; Manufacturer: WCON; Manufacturer Part Number: 3710-6001OS0B05; Part number NEMS: 100500728; Pad Count: 2; Note: N.A.; Component Status: Active; System: Connector
L5 L6 = L0806-2µ2-2500mA-73mOhm-CIGT201610EH2R2MNE: Inductor, Irms=2.5A, Isat=2.9A, ±20%, DCR=73mΩ; Manufacturer: Samsung Electro-Mechanics America; Part number Norautron: 26521789; Part number NEMS: 100300400; Component Status: Active; Pad Count: 2; Note: Unshielded Thin Film Inductor; Artikkelnr Noca: N.A.
P14 P16 = Pin List 1x3 SMD: Pin List 1x3, 2.54mm (100mil), SMD; Manufacturer: WCON; Manufacturer Part Number: 1125-1103S0M116CR04; Part number Norautron: 26470016; Part number NEMS: 100500306; Note: N.A.; Pad Count: 3; Component Status: Active; System: Connector
Q2 Q3 = MCM2301-TP: Dual P-Channel MOFET, 3.8A, 90mOhm max, 1.4W; Manufacturer: Micro Commercial Components; Part number NEMS: 101300199; Component Status: Active; Pad Count: 6; Note: N.A.
Q8 = PBSS4330PA,115: 30V, 3A, 2.1W, G=270, NPN Transistor; Manufacturer: Nexperia; Part number NEMS: 101300184; Component Status: Active; Pad Count: 3; Note: N.A.
R14 R16 = R0402-0R: Resistor, ±5%, 0.063W; Manufacturer: N.A.; Part number IPS: 00000007128; Part number NEMS: 100100109; Component Status: Active; Pad Count: 2; Note: Chip Res 5%; Artikkelnr Noca: 27049000
R15 = R0402-10R: Resistor, ±1%, 0.063W; Manufacturer: N.A.; Part number NEMS: 100100126; Component Status: Active; Pad Count: 2; Value: 10R; Note: Chip Res 1%; Artikkelnr Noca: 27049025; Assembly: Not mounted
R17 = R0201-47k: Resistor, ±1%, 0.05W; Manufacturer: N.A.; Part number IPS: 00000001423; Part number NEMS: 100100076; Component Status: Active; Pad Count: 2; Note: Chip Res 1%
R18 = R0201-4k7: Resistor, ±1%, 0.05W; Manufacturer: N.A.; Part number IPS: 00000001706; Part number NEMS: 100100061; Component Status: Active; Pad Count: 2; Note: Chip Res 1%
R20 R24 = R0201-1M0: Resistor, ±1%, 0.05W; Manufacturer: N.A.; Part number IPS: 00000001418; Part number Norautron: 26107108; Part number NEMS: 100100093; Note: Chip Res 1%; Pad Count: 2; Component Status: Active
R21 R22 = R0201-10k: Resistor, ±1%, 0.05W; Manufacturer: N.A.; Part number IPS: 00000001255; Part number Norautron: 26107101; Part number NEMS: 100100065; Note: Chip Res 1%; Pad Count: 2; Component Status: Active
R23 = R0201-100k: as R7 on sheet pca10184_debugger_mcu
R52 R54 = R0201-0R: Resistor, ±5%, 0.05W; Manufacturer: N.A.; Part number IPS: 00000003245; Part number NEMS: 100100001; Component Status: Active; Pad Count: 2; Note: Chip Res 5%
R53 = R0201-10k: Resistor, ±1%, 0.05W; Manufacturer: N.A.; Part number IPS: 00000001255; Part number Norautron: 26107101; Part number NEMS: 100100065; Component Status: Active; Pad Count: 2; Note: Chip Res 1%
R55 = R0201-33k: Resistor, ±1%, 0.05W; Manufacturer: N.A.; Part number IPS: 00000001708; Part number NEMS: 100100073; Component Status: Active; Pad Count: 2; Note: Chip Res 1%
SB6 SB18 SB31 = Solderbridge Shorted Power: Shorted Solderbridge Power; Manufacturer: N.A.; Part number NEMS: 100500460; Component Status: Active; Pad Count: 2; System: Connector
SB17 = Solderbridge: as SB25 on sheet pca10184_top_level
SB19-SB21 SB27 SB30 = Solderbridge: Manufacturer: N.A.; Part number NEMS: 100500458; Component Status: Active; Pad Count: 2; System: Connector
SB28 SB29 = Solderbridge Shorted: Shorted Solderbridge; Manufacturer: N.A.; Part number NEMS: 100500459; Component Status: Active; Pad Count: 2; System: Connector
SW5 = Switch-Slide-RA-J-Lead-DPDT-8.5x3.5mm_C&K: SMD slide Switch (ON-ON); Manufacturer: C&K; Manufacturer Part Number: JS202011JAQN; Part number IPS: 00000007811; Part number NEMS: 101500037; Note: N.A.; Pad Count: 6; Component Status: Active
TP1 TP2 TP4-TP6 TP14 TP16-TP20 = TP_SMD_Ø1.5MM: as TP7 on sheet pca10184_debugger_mcu
TP15 = TP - S1751-46R: PC TEST POINT TIN SMD L; Manufacturer: Harwin; Part number NEMS: 100500525; Component Status: Active; Pad Count: 1; Note: N.A.
TP35 = TP_SMD_Ø0.7MM: 0.7mm circular SMD testpad; Manufacturer: Nordic Semiconductor; Manufacturer Part Number: N.A.; Part number NEMS: 100500474; Pad Count: 1; Component Status: Active
U3 = nPM1300-QEAA: Li-Ion/Li-Polymer USB-C battery charger with high efficiency buck regulators, LDOs or load switches, LED drivers, TWI and VBUSOUT; Manufacturer: Nordic Semiconductor; Part number NEMS: 102000291; Component Status: Active; Pad Count: 33; Note: N.A.
U9 = TLV271CW5-7: Dual rail to rail CMOS Amplifier; Manufacturer: Diodes Incorporated; Part number NEMS: 101900398; Component Status: Active; Pad Count: 5; Note: N.A.

## Sheet pca10184_nrf54lm20.SchDoc: =ProductName + ' - nRF54L20 MCU'
size A3; Organization: Nordic Semiconductor; DocumentNumber: 2; Revision: 0.3.4; SheetNumber: 2; SheetTotal: 9; Author: GETR; CompanyName: Nordic Semiconductor; DrawnBy: GETR; DocumentSize: A3
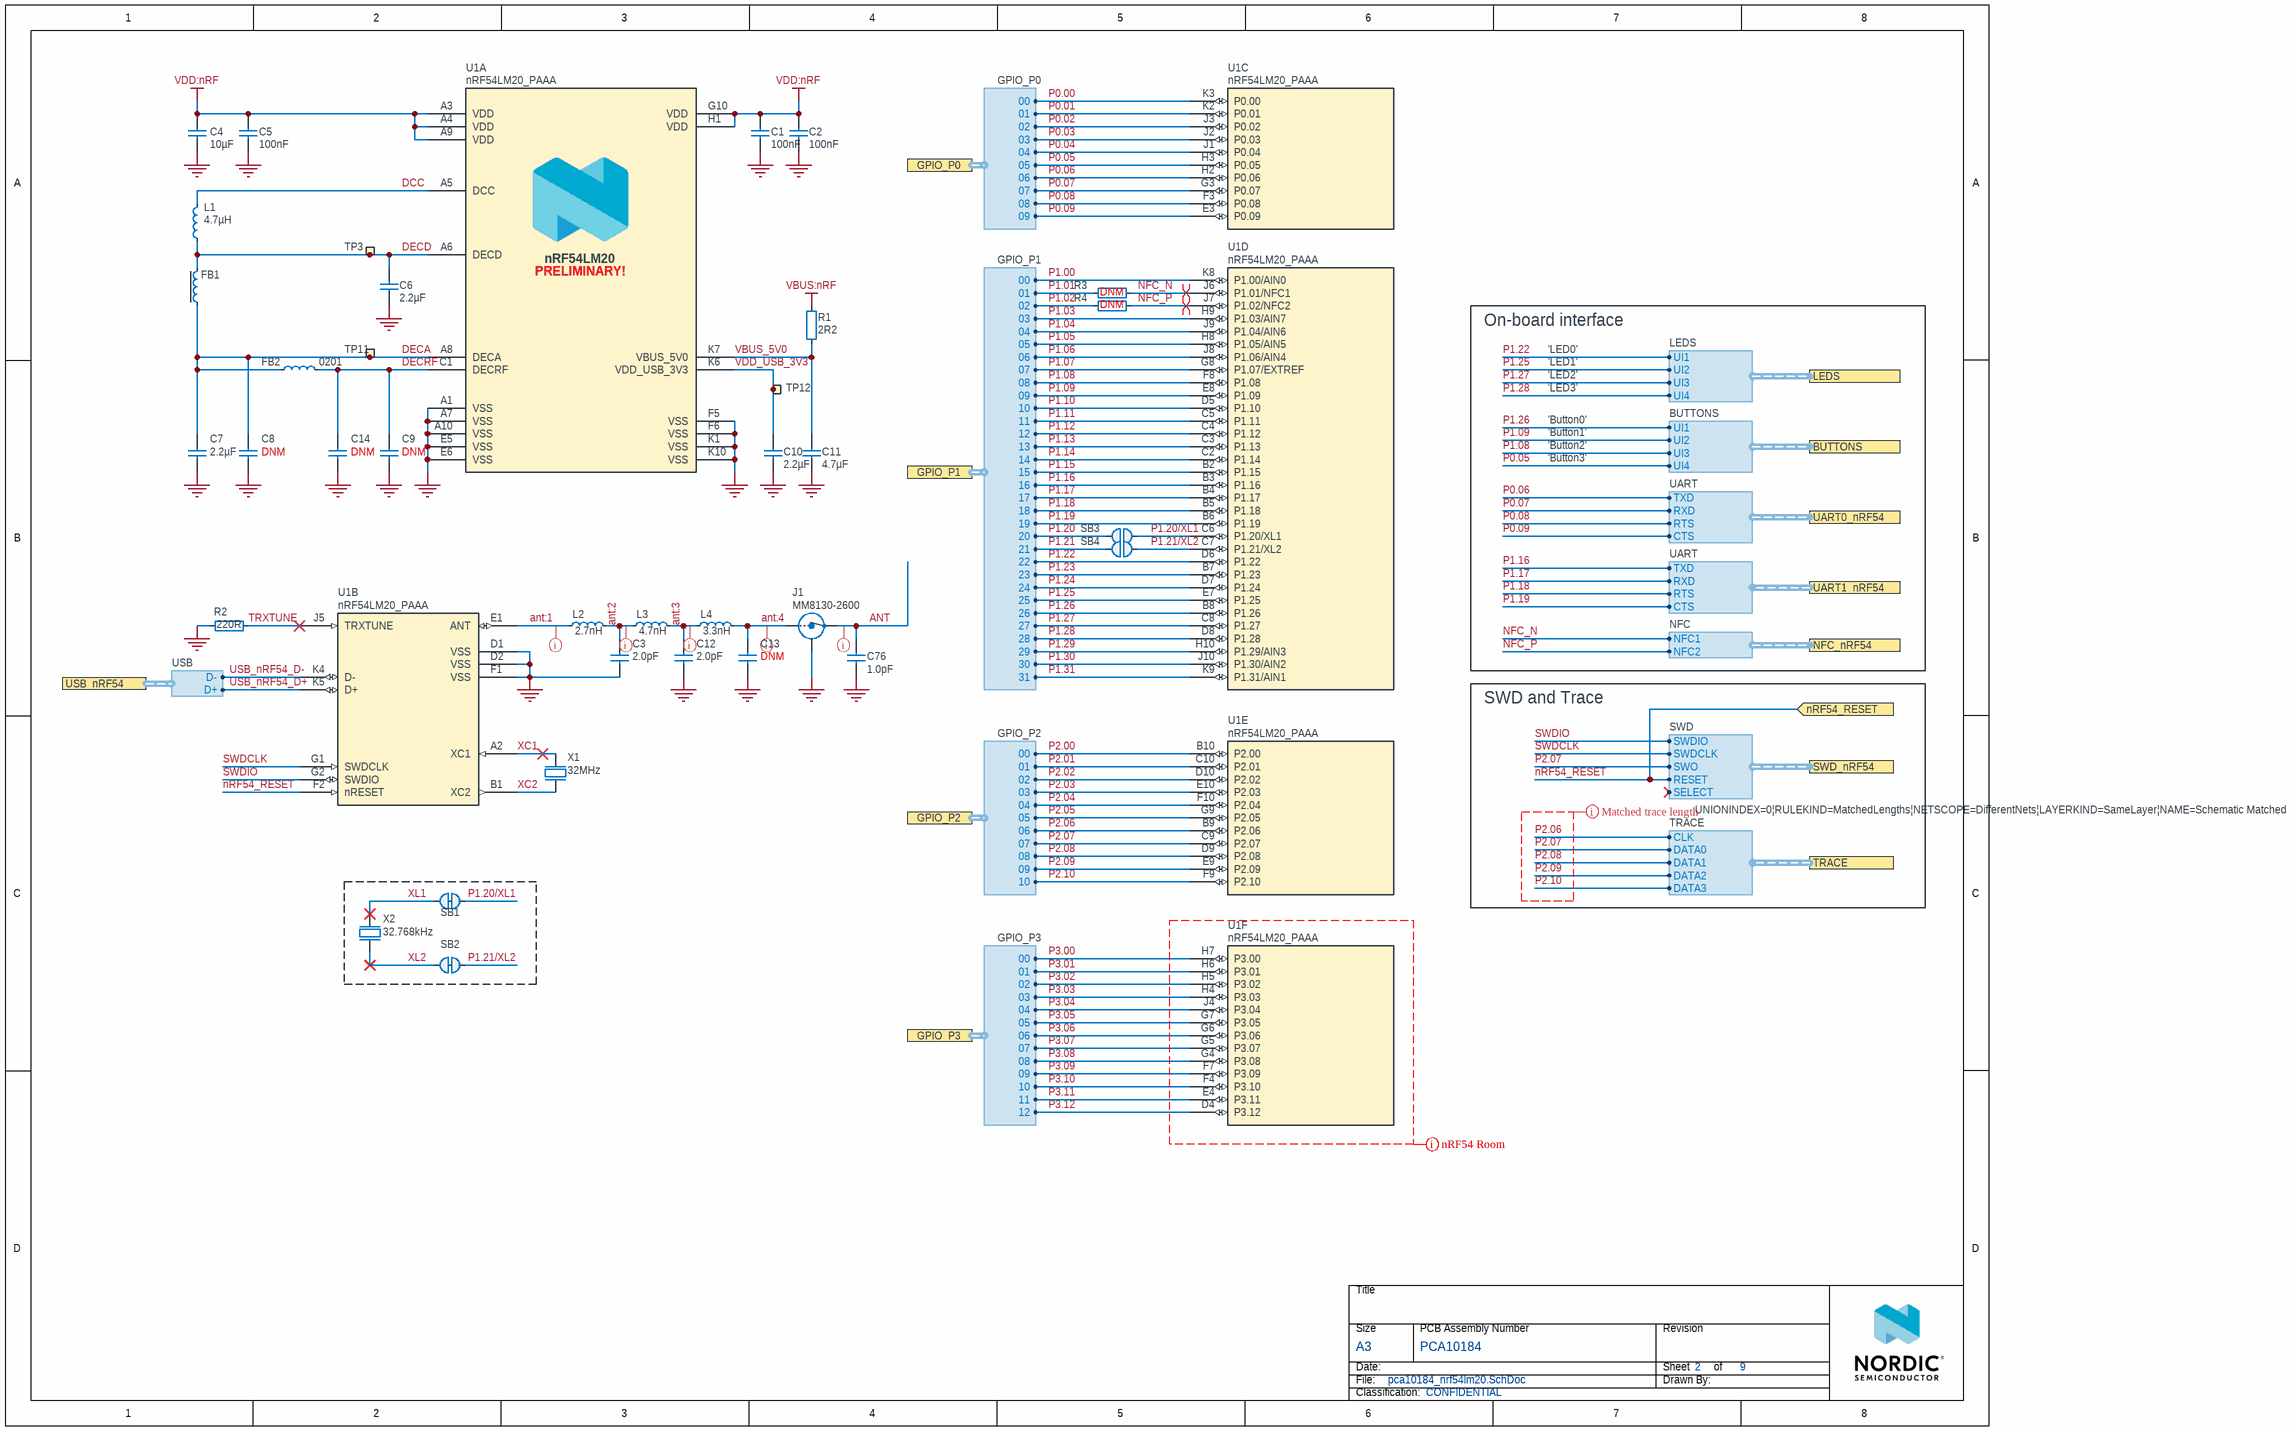
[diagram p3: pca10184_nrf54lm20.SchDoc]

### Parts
C1  100nF  [CAPC0603X03L_C]
C2  100nF  [CAPC0603X03L_C]
C3  2.0pF  [CAPC0603X03L_C]
C4  10µF  [CAPC1005X04L]
C5  100nF  [CAPC0603X03L_C]
C6  2.2µF  [CAPC0603X03L_C]
C7  2.2µF  [CAPC0603X03L_C]
C8  DNM  [CAPC0603X03L_C]
C9  DNM  [CAPC0603X03L_C]
C10  2.2µF  [CAPC0603X03L_C]
C11  4.7µF  [CAPC1005X04L]
C12  2.0pF  [CAPC0603X03L_C]
C13  DNM  [CAPC0603X03L_C_NC]
C14  DNM  [CAPC0603X03L_C]
C76  1.0pF  [CAPC0603X03L_C]
FB1  120R/0.2A  [INDC0603X03L_C]  (value not drawn)
FB2  Footprint Doc: 0201  [INDC0603X03L_C]  (hidden comment: 15nH)
J1  MM8130-2600  [COAXIAL-SWF]
L1  4.7µH  [INDC1608X06L]
L2  2.7nH  [INDC0603X03L_C]
L3  4.7nH  [INDC0603X03L_C]
L4  3.3nH  [INDC0603X03L_C]
R1  2R2  [RESC1608X06L]
R2  220R  [RESC0603X03L_C]
R3  DNM  [RESC1005X04L_NC]
R4  DNM  [RESC1005X04L_NC]
SB1  Solderbridge  [Solderbridge_Shorted]  (value not drawn)  (net tie, no BOM)
SB2  Solderbridge  [Solderbridge_Shorted]  (value not drawn)  (net tie, no BOM)
SB3  Solderbridge  [Solderbridge]  (value not drawn)  (no BOM)
SB4  Solderbridge  [Solderbridge]  (value not drawn)  (no BOM)
TP3  Ø0.7mm,SMD  [TP_SMD_D0.7mm]  (value not drawn)  (no BOM)
TP11  Ø0.7mm,SMD  [TP_SMD_D0.7mm]  (value not drawn)  (no BOM)
TP12  Ø0.7mm,SMD  [TP_SMD_D0.7mm]  (value not drawn)  (no BOM)
U1  nRF54LM20_PAAA  [BGA98C35P10X10_367X385X86]  (parts A,B,C,D,E,F of 6)
X1  32MHz  [BT-XTAL_2016]
X2  32.768kHz  [XTAL_2012]

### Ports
BUTTONS (harness BUTTONS), GPIO_P0 (harness GPIO_P0), GPIO_P1 (harness GPIO_P1), GPIO_P2 (harness GPIO_P2), GPIO_P3 (harness GPIO_P3), LEDS (harness LEDS), NFC_nRF54 (harness NFC), nRF54_RESET (in), SWD_nRF54 (harness SWD), TRACE (harness TRACE), UART0_nRF54 (harness UART), UART1_nRF54 (harness UART), USB_nRF54 (harness USB)

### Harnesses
GPIO_P0: 00, 01, 02, 03, 04, 05, 06, 07, 08, 09
GPIO_P1: 00, 01, 02, 03, 04, 05, 06, 07, 08, 09, 10, 11, 12, 13, 14, 15, 16, 17, 18, 19, 20, 21, 22, 23, 24, 25, 26, 27, 28, 29, 30, 31
GPIO_P2: 00, 01, 02, 03, 04, 05, 06, 07, 08, 09, 10
GPIO_P3: 00, 01, 02, 03, 04, 05, 06, 07, 08, 09, 10, 11, 12
USB: D+, D-
NFC: NFC2, NFC1
UART: RTS, CTS, RXD, TXD
LEDS: UI2, UI1, UI3, UI4
BUTTONS: UI2, UI1, UI3, UI4
SWD: SWDIO, SWDCLK, SWO, RESET, SELECT
TRACE: CLK, DATA0, DATA1, DATA3, DATA2

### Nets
GND: C1.2 C2.2 C3.1 C4.1 C5.2 C6.1 C7.1 C8.1 C9.1 C10.1 C11.1 C12.1 C13.1 C14.1 C76.1 J1.2(Shield) R2.1 U1.A1(VSS) U1.A7(VSS) U1.A10(VSS) U1.D1(VSS) U1.D2(VSS) U1.E5(VSS) U1.E6(VSS) U1.F1(VSS) U1.F5(VSS) U1.F6(VSS) U1.K1(VSS) U1.K10(VSS) X1.2(GND) X1.4(GND)
VBUS:nRF: R1.2
VDD:nRF: C1.1 C2.1 C4.2 C5.1 U1.A3(VDD) U1.A4(VDD) U1.A9(VDD) U1.G10(VDD) U1.H1(VDD)
ANT: C76.2 J1.3(OUT)
ant:1: L2.1 U1.E1(ANT)
ant:2: C3.2 L2.2 L3.1
ant:3: C12.2 L3.2 L4.1
ant:4: C13.2 J1.1(IN) L4.2
DCC: L1.1 U1.A5(DCC)
DECA: C7.2 C8.2 FB1.2 FB2.2 TP11.1 U1.A8(DECA)
DECD: C6.2 FB1.1 L1.2 TP3.1 U1.A6(DECD)
DECRF: C9.2 C14.2 FB2.1 U1.C1(DECRF)
NFC_N: R3.2 U1.J6(P1.01/NFC1) ; port NFC_nRF54.NFC1
NFC_P: R4.2 U1.J7(P1.02/NFC2) ; port NFC_nRF54.NFC2
nRF54_RESET: U1.F2(nRESET) ; port nRF54_RESET, port SWD_nRF54.RESET
P0.00: U1.K3(P0.00) ; port GPIO_P0.00
P0.01: U1.K2(P0.01) ; port GPIO_P0.01
P0.02: U1.J3(P0.02) ; port GPIO_P0.02
P0.03: U1.J2(P0.03) ; port GPIO_P0.03
P0.04: U1.J1(P0.04) ; port GPIO_P0.04
P0.05: U1.H3(P0.05) ; port GPIO_P0.05, port BUTTONS.UI4
P0.06: U1.H2(P0.06) ; port GPIO_P0.06, port UART0_nRF54.TXD
P0.07: U1.G3(P0.07) ; port GPIO_P0.07, port UART0_nRF54.RXD
P0.08: U1.F3(P0.08) ; port GPIO_P0.08, port UART0_nRF54.RTS
P0.09: U1.E3(P0.09) ; port GPIO_P0.09, port UART0_nRF54.CTS
P1.00: U1.K8(P1.00/AIN0) ; port GPIO_P1.00
P1.01: R3.1 ; port GPIO_P1.01
P1.02: R4.1 ; port GPIO_P1.02
P1.03: U1.H9(P1.03/AIN7) ; port GPIO_P1.03
P1.04: U1.J9(P1.04/AIN6) ; port GPIO_P1.04
P1.05: U1.H8(P1.05/AIN5) ; port GPIO_P1.05
P1.06: U1.J8(P1.06/AIN4) ; port GPIO_P1.06
P1.07: U1.G8(P1.07/EXTREF) ; port GPIO_P1.07
P1.08: U1.F8(P1.08) ; port GPIO_P1.08, port BUTTONS.UI3
P1.09: U1.E8(P1.09) ; port GPIO_P1.09, port BUTTONS.UI2
P1.10: U1.D5(P1.10) ; port GPIO_P1.10
P1.11: U1.C5(P1.11) ; port GPIO_P1.11
P1.12: U1.C4(P1.12) ; port GPIO_P1.12
P1.13: U1.C3(P1.13) ; port GPIO_P1.13
P1.14: U1.C2(P1.14) ; port GPIO_P1.14
P1.15: U1.B2(P1.15) ; port GPIO_P1.15
P1.16: U1.B3(P1.16) ; port GPIO_P1.16, port UART1_nRF54.TXD
P1.17: U1.B4(P1.17) ; port GPIO_P1.17, port UART1_nRF54.RXD
P1.18: U1.B5(P1.18) ; port GPIO_P1.18, port UART1_nRF54.RTS
P1.19: U1.B6(P1.19) ; port GPIO_P1.19, port UART1_nRF54.CTS
P1.20: SB3.2 ; port GPIO_P1.20
P1.20/XL1: SB1.1 SB3.1 U1.C6(P1.20/XL1)
P1.21: SB4.2 ; port GPIO_P1.21
P1.21/XL2: SB2.1 SB4.1 U1.C7(P1.21/XL2)
P1.22: U1.D6(P1.22) ; port GPIO_P1.22, port LEDS.UI1
P1.23: U1.B7(P1.23) ; port GPIO_P1.23
P1.24: U1.D7(P1.24) ; port GPIO_P1.24
P1.25: U1.E7(P1.25) ; port GPIO_P1.25, port LEDS.UI2
P1.26: U1.B8(P1.26) ; port GPIO_P1.26, port BUTTONS.UI1
P1.27: U1.C8(P1.27) ; port GPIO_P1.27, port LEDS.UI3
P1.28: U1.D8(P1.28) ; port GPIO_P1.28, port LEDS.UI4
P1.29: U1.H10(P1.29/AIN3) ; port GPIO_P1.29
P1.30: U1.J10(P1.30/AIN2) ; port GPIO_P1.30
P1.31: U1.K9(P1.31/AIN1) ; port GPIO_P1.31
P2.00: U1.B10(P2.00) ; port GPIO_P2.00
P2.01: U1.C10(P2.01) ; port GPIO_P2.01
P2.02: U1.D10(P2.02) ; port GPIO_P2.02
P2.03: U1.E10(P2.03) ; port GPIO_P2.03
P2.04: U1.F10(P2.04) ; port GPIO_P2.04
P2.05: U1.G9(P2.05) ; port GPIO_P2.05
P2.06: U1.B9(P2.06) ; port GPIO_P2.06, port TRACE.CLK
P2.07: U1.C9(P2.07) ; port GPIO_P2.07, port SWD_nRF54.SWO, port TRACE.DATA0
P2.08: U1.D9(P2.08) ; port GPIO_P2.08, port TRACE.DATA1
P2.09: U1.E9(P2.09) ; port GPIO_P2.09, port TRACE.DATA2
P2.10: U1.F9(P2.10) ; port GPIO_P2.10, port TRACE.DATA3
P3.00: U1.H7(P3.00) ; port GPIO_P3.00
P3.01: U1.H6(P3.01) ; port GPIO_P3.01
P3.02: U1.H5(P3.02) ; port GPIO_P3.02
P3.03: U1.H4(P3.03) ; port GPIO_P3.03
P3.04: U1.J4(P3.04) ; port GPIO_P3.04
P3.05: U1.G7(P3.05) ; port GPIO_P3.05
P3.06: U1.G6(P3.06) ; port GPIO_P3.06
P3.07: U1.G5(P3.07) ; port GPIO_P3.07
P3.08: U1.G4(P3.08) ; port GPIO_P3.08
P3.09: U1.F7(P3.09) ; port GPIO_P3.09
P3.10: U1.F4(P3.10) ; port GPIO_P3.10
P3.11: U1.E4(P3.11) ; port GPIO_P3.11
P3.12: U1.D4(P3.12) ; port GPIO_P3.12
SWDCLK: U1.G1(SWDCLK) ; port SWD_nRF54.SWDCLK
SWDIO: U1.G2(SWDIO) ; port SWD_nRF54.SWDIO
TRXTUNE: R2.2 U1.J5(TRXTUNE)
USB_nRF54_D+: U1.K5(D+) ; port USB_nRF54.D+
USB_nRF54_D-: U1.K4(D-) ; port USB_nRF54.D-
VBUS_5V0: C11.2 R1.1 U1.K7(VBUS_5V0)
VDD_USB_3V3: C10.2 TP12.1 U1.K6(VDD_USB_3V3)
XC1: U1.A2(XC1) X1.1(inp)
XC2: U1.B1(XC2) X1.3(out)
XL1: SB1.2 X2.2(out)
XL2: SB2.2 X2.1(inp)

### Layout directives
differential pair; differential pair class NFC: NFC_N, NFC_P
net class TRACE; rule Matched Net Lengths [Delay Tolerance = 500ps]: P2.06, P2.07, P2.08, P2.09, P2.10
net class RF: ANT, ant:1, ant:2, ant:3, ant:4
CompClassName: nRF54: (no net found under the mark)

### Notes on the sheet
- On-board interface
- 'LED0'
- 'LED1'
- 'LED2'
- 'LED3'
- 'Button0'
- 'Button1'
- 'Button2'
- 'Button3'
- SWD and Trace

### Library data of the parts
C1 C2 C5 = C0201-100n-10V-X7R: Capacitor, X7R, ±10%, 10V; Manufacturer: N.A.; Part number NEMS: 100200469; Pad Count: 2; Component Status: Active
C3 C12 = C0201-2.0p-HQ-Murata: Capacitor, NP0, ±0.05pF, 25V; Manufacturer: Murata; Manufacturer Part Number: GJM0335C1E2R0WB01; Part number IPS: 00000001775; Part number NEMS: 100200419; Component Status: Active; Pad Count: 2; Artikkelnr Noca: N.A.
C4 = C0402-10µF-6.3V-X6S: Capacitor, X6S, ±20%, 6.3V; Manufacturer: N.A.; Part number NEMS: 100200478; Component Status: Active; Pad Count: 2
C6 C7 C10 = C0201-2µ2-10V-X5R-GRM033R61A225KE47: Capacitor, Ceramic, 2.2µF 10V X5R 0201,±10%; Manufacturer: Murata; Manufacturer Part Number: GRM033R61A225KE47D; Part number NEMS: 100200496; Component Status: Active; Pad Count: 2; Artikkelnr Noca: N.A.
C8 = C0201-10n-6.3V-X7R: Capacitor, X7R, 6.3V; Manufacturer: Murata; Manufacturer Part Number: GRM033R70J103KA01D; Part number NEMS: 100200407; Component Status: Active; Pad Count: 2; Value: 10nF; Artikkelnr Noca: N.A.; Assembly: Not mounted
C9 = C0201-3.9p-HQ-Murata: Capacitor, NP0, ±0.05pF, 25V; Manufacturer: Murata; Manufacturer Part Number: GJM0333C1E3R9WB01; Part number NEMS: 100200424,100200024; Component Status: Active; Pad Count: 2; Value: 3.9pF; Artikkelnr Noca: N.A.; Assembly: Not mounted
C11 = C0402-4µ7-10V-X5R: Capacitor, X5R, 10V; Manufacturer: Murata; Manufacturer Part Number: GRM155R61A475MEAAD; Part number NEMS: 100200415; Component Status: Active; Pad Count: 2; Artikkelnr Noca: N.A.
C13 = C0201-N.C.: Not mounted; Manufacturer: N.A.; Part number NEMS: 100200001; Component Status: Active; Pad Count: 2; Value: N.C.; Note: Chip Cap; Assembly: Not mounted
C14 = C0201-2µ2-2.5V-X6T-GRM033D80E225ME47D: Capacitor, Ceramic, 2.2µF 2.5V X6T 0201,±20%; Manufacturer: Murata; Manufacturer Part Number: GRM033R61A225KE47; Part number NEMS: 100200527; Component Status: Active; Pad Count: 2; Note: 2.5V, 20%, X6T; Artikkelnr Noca: N.A.; Assembly: Not mounted
C76 = C0201-1.0p_RF: RF Chip Cap 0201; Manufacturer: N.A.; Part number NEMS: 100200085; Pad Count: 2; Note: High frequency chip capasitors ±5%, NP0; Component Status: Active
FB1 = FB0201-120R@100M-200mA-BLM03AG121SN1D: Ferrite Bead, 120 Ohm @ 100MHz, 200mA, 500 mOhm Max; Manufacturer: Murata; Part number NEMS: 100300419; Component Status: Active; Pad Count: 2; Artikkelnr Noca: N.A.
FB2 = L0201-15n: Inductor, 250mA, ±5%; Manufacturer: Murata; Manufacturer Part Number: LQP03TN15NJ02D; Part number NEMS: 100300032; Component Status: Active; Pad Count: 2; Note: High frequency chip inductor ±10%; Artikkelnr Noca: N.A.
J1 = MM8130-2600: Coaxial Connector with Switch; Manufacturer: Murata; Part number IPS: 00000009955; Part number Norautron: 26030338; Part number NEMS: 100500400; Note: N.A.; Artikkelnr Noca: 55029011; Pad Count: 3; Component Status: Active
L1 = L0603-4µ7-MLZ1608M4R7WT000: Inductor, 120mA, ±20%, 0.65R; Manufacturer: TDK Corporation; Part number NEMS: 100300440; Component Status: Active; Pad Count: 2; Note: Power Inductor ±20%; Artikkelnr Noca: N.A.
L2 = L0201-2n7-HQ-Murata: Inductor, 600mA, ±0.1ｎH, 120mOhm; Manufacturer: Murata; Manufacturer Part Number: LQP03HQ2N7B02; Part number IPS: 00000001753; Part number NEMS: 100300214; Component Status: Active; Pad Count: 2; Note: -55°C ~ 125°C; Artikkelnr Noca: N.A.
L3 = L0201-4n7-Wirewound-Murata: Inductor, 620mA, ±5%, 90mOhm, Q=45; Manufacturer: Murata; Manufacturer Part Number: LQW03AW4N7J00; Part number IPS: 00000001790; Part number NEMS: 100300175; Component Status: Active; Pad Count: 2; Note: -55°C ~ 125°C; Artikkelnr Noca: N.A.
L4 = L0201-3n3-HQ-Murata: Inductor, 500mA, ±0.1ｎH, 170mOhm; Manufacturer: Murata; Manufacturer Part Number: LQP03HQ3N3B02; Part number NEMS: 100300220; Component Status: Active; Pad Count: 2; Note: -55°C ~ 125°C; Artikkelnr Noca: N.A.
R1 = R0603-2R2: RES 2.2 OHM 1% 1/10W 0603; Manufacturer: N.A.; Part number NEMS: 100100736; Component Status: Active; Pad Count: 2; Note: Chip Res 1%
R2 = R0201-220: Resistor, ±1%, 0.05W; Manufacturer: N.A.; Part number IPS: 00000000863; Part number Norautron: 26107014; Part number NEMS: 100100032; Component Status: Active; Pad Count: 2; Note: Chip Res 1%
R3 R4 = R0402-N.C.: Not mounted; Manufacturer: N.A.; Part number NEMS: 100100281; Component Status: Active; Pad Count: 2; Value: N.C.; Note: Chip Res; Assembly: Not mounted
SB1 SB2 = Solderbridge Shorted: as SB26 on sheet pca10184_top_level
SB3 SB4 = Solderbridge: as SB25 on sheet pca10184_top_level
TP3 TP11 TP12 = TP_SMD_Ø0.7MM: as TP35 on sheet pca10184_power_supply
U1 = nRF54LM20-PAAA: nRF54 series BLE; Manufacturer: Nordic Semiconductor; Part number NEMS: 102000394; Component Status: Active; Pad Count: 98; Note: N.A.
X1 = XTAL_SMD2016_32MHz_8pF_Kyocera: XTAL SMD 2016, 32MHz, Cl=8pF, Tot: ±40ppm; Manufacturer Part Number: CX2016DB32000D0WZRC1; Part number IPS: 00000007827; Part number Norautron: 26511136; Part number NEMS: 101600039; Component Status: Active; Pad Count: 4; Note: XTAL SMD 32.000MHz; Artikkelnr Noca: 22010022
X2 = XTAL_SMD2012_32.768kHz_9pF_TXC: XTAL SMD 2012, 32.768kHz, 9pF, ±20ppm; Manufacturer: TXC Corporation; Manufacturer Part Number: 9HT11-32.768KDZC-T; Part number NEMS: 101600107; Component Status: Active; Pad Count: 2; Note: XTAL SMD 32.768kHz; Artikkelnr Noca: N.A.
